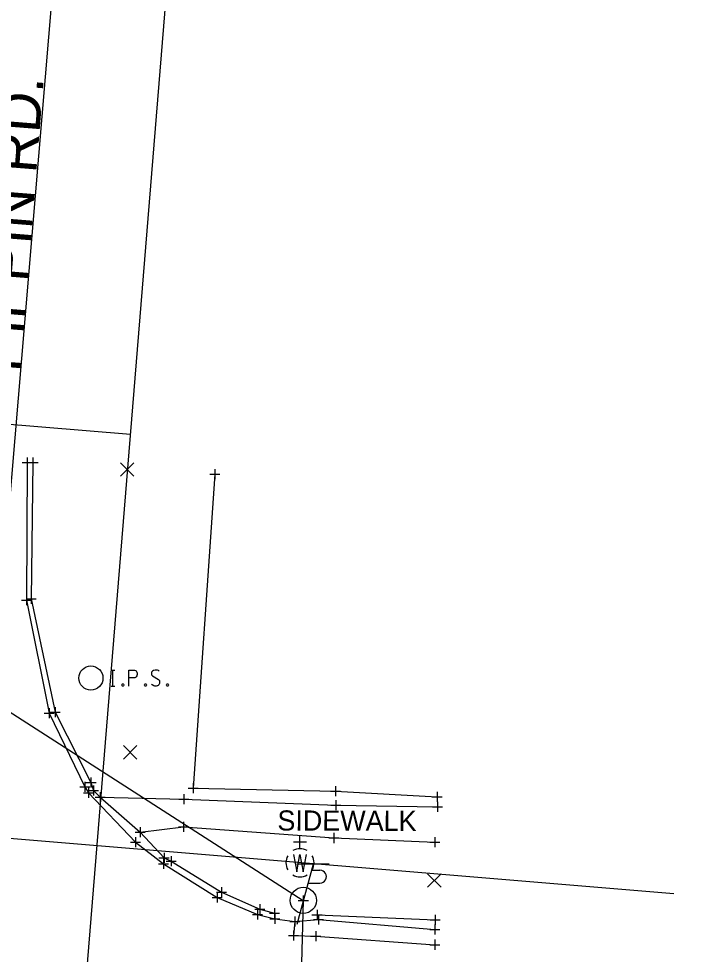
# Model space of a CAD drawing. Extents: x 1380440 to 1381945, y 468756 to 470369.
# Drawn here: x 1381547.1 to 1381614.9, y 469159.2 to 469252.2 of the extents above; entities that cross this region are included whole.
import ezdxf

# ---------------------------------------------------------------- set-up
doc = ezdxf.new("R2010")
doc.units = 0
for name, color, linetype in [('DR_P_Headwall', 7, 'Continuous'), ('DR_X_Cells', 7, 'Continuous'), ('GE_P_Driveway_CL', 7, 'Continuous'), ('GK_Drainage_Nodes', 7, 'Continuous'), ('PV_P_Walk', 7, 'Continuous'), ('PV_X_COP', 7, 'Continuous'), ('RW_P_Const_Limits', 7, 'Continuous'), ('RW_P_Esmt_TMP', 7, 'Continuous'), ('SH_Named_Boundary', 7, 'Continuous'), ('UT_X_Overhead_Combined', 7, 'Continuous'), ('UT_X_Overhead_Telecom', 7, 'Continuous'), ('UT_X_Sanitary_Line', 7, 'Continuous'), ('UT_X_Water', 7, 'Continuous'), ('X-SUBDIVISION', 7, 'Continuous')]:
    doc.layers.add(name, color=color, linetype=linetype)

msp = doc.modelspace()

# ---------------------------------------------------------------- linework, layer by layer
at = {"layer": 'DR_P_Headwall'}
for points in [[(1381555.163, 469174.772), (1381563.486, 469174.57), (1381578.581, 469173.981), (1381588.68, 469173.803)], [(1381559.145, 469171.286), (1381563.442, 469171.834), (1381578.369, 469170.714), (1381588.407, 469170.306)]]:
    msp.add_lwpolyline(points, dxfattribs=at)
at = {"layer": 'DR_X_Cells'}
for points in [[(1381548.49, 469208.03), (1381548.306, 469194.482), (1381550.699, 469183.223), (1381554.254, 469176.228), (1381554.509, 469175.447), (1381555.163, 469174.772), (1381559.145, 469171.286), (1381561.509, 469168.737), (1381562.206, 469168.402), (1381567.213, 469165.329), (1381571.015, 469163.646), (1381572.481, 469163.233)], [(1381576.709, 469163.068), (1381588.441, 469162.58)], [(1381574.504, 469162.404), (1381576.844, 469162.602), (1381588.409, 469161.614)]]:
    msp.add_lwpolyline(points, dxfattribs=at)
at = {"layer": 'GE_P_Driveway_CL'}
for p, q in [((1381557.169, 469206.688), (1381558.503, 469208.023)), ((1381557.169, 469208.023), (1381558.503, 469206.688)), ((1381557.47, 469178.556), (1381558.804, 469179.891)), ((1381557.47, 469179.891), (1381558.804, 469178.556)), ((1381587.693, 469165.821), (1381589.027, 469167.156)), ((1381587.693, 469167.156), (1381589.027, 469165.821))]:
    msp.add_line(p, q, dxfattribs=at)
at = {"layer": 'GK_Drainage_Nodes'}
msp.add_lwpolyline([(1381566.566, 469206.867), (1381564.411, 469175.674), (1381578.548, 469175.359), (1381588.639, 469174.792)], dxfattribs=at)
at = {"layer": 'PV_P_Walk'}
for points in [[(1381556.263, 469187.412), (1381556.616, 469187.412)], [(1381556.439, 469185.812), (1381556.439, 469187.412)], [(1381558.005, 469185.812), (1381558.005, 469187.412), (1381558.534, 469187.412), (1381558.589, 469187.4), (1381558.666, 469187.374), (1381558.699, 469187.349), (1381558.732, 469187.324), (1381558.776, 469187.261), (1381558.809, 469187.198), (1381558.831, 469187.097), (1381558.831, 469186.946), (1381558.82, 469186.896), (1381558.798, 469186.82), (1381558.754, 469186.732), (1381558.71, 469186.694), (1381558.677, 469186.669), (1381558.622, 469186.644), (1381558.534, 469186.631), (1381558.005, 469186.631)], [(1381561.014, 469187.299), (1381560.992, 469187.324), (1381560.959, 469187.349), (1381560.86, 469187.387), (1381560.738, 469187.412), (1381560.65, 469187.412), (1381560.617, 469187.412), (1381560.474, 469187.374), (1381560.353, 469187.299), (1381560.275, 469187.198), (1381560.253, 469187.097), (1381560.253, 469187.022), (1381560.275, 469186.921), (1381560.364, 469186.833), (1381560.97, 469186.455), (1381561.025, 469186.405), (1381561.047, 469186.354), (1381561.069, 469186.279), (1381561.069, 469186.203), (1381561.058, 469186.127), (1381561.047, 469186.077), (1381561.025, 469186.014), (1381561.003, 469185.964), (1381560.981, 469185.926), (1381560.948, 469185.888), (1381560.915, 469185.863), (1381560.871, 469185.838), (1381560.838, 469185.825), (1381560.738, 469185.812), (1381560.584, 469185.812), (1381560.485, 469185.838), (1381560.341, 469185.926), (1381560.253, 469186.001)], [(1381557.398, 469186.027), (1381557.453, 469186.027), (1381557.487, 469186.001), (1381557.52, 469185.951), (1381557.52, 469185.888), (1381557.487, 469185.838), (1381557.453, 469185.812), (1381557.398, 469185.812), (1381557.365, 469185.838), (1381557.332, 469185.888), (1381557.332, 469185.951), (1381557.365, 469186.001), (1381557.398, 469186.027)], [(1381559.647, 469186.027), (1381559.702, 469186.027), (1381559.735, 469186.001), (1381559.768, 469185.951), (1381559.768, 469185.888), (1381559.735, 469185.838), (1381559.702, 469185.812), (1381559.647, 469185.812), (1381559.614, 469185.838), (1381559.581, 469185.888), (1381559.581, 469185.951), (1381559.614, 469186.001), (1381559.647, 469186.027)], [(1381561.83, 469186.027), (1381561.885, 469186.027), (1381561.918, 469186.001), (1381561.951, 469185.951), (1381561.951, 469185.888), (1381561.918, 469185.838), (1381561.885, 469185.812), (1381561.83, 469185.812), (1381561.796, 469185.838), (1381561.764, 469185.888), (1381561.764, 469185.951), (1381561.796, 469186.001), (1381561.83, 469186.027)], [(1381556.263, 469185.812), (1381556.616, 469185.812)]]:
    msp.add_lwpolyline(points, dxfattribs=at)
msp.add_circle((1381554.244, 469186.611), 1.2, dxfattribs=at)
at = {"layer": 'PV_X_COP'}
for p, q in [((1381576.312, 469168.111), (1381574.706, 469162.111)), ((1381577.912, 469168.111), (1381574.712, 469168.111)), ((1381576.152, 469167.511), (1381577.002, 469167.511)), ((1381575.811, 469166.236), (1381577.002, 469166.236))]:
    msp.add_line(p, q, dxfattribs=at)
msp.add_circle((1381575.349, 469164.511), 1.3, dxfattribs=at)
msp.add_arc((1381577.015, 469166.874), 0.638, 268.8767, 91.1233, dxfattribs=at)
at = {"layer": 'RW_P_Const_Limits'}
for p, q in [((1381575.652, 469170.283), (1381574.38, 469170.283)), ((1381575.017, 469169.646), (1381575.017, 469170.918)), ((1381575.017, 469168.246), (1381575.017, 469168.246))]:
    msp.add_line(p, q, dxfattribs=at)
msp.add_lwpolyline([(1381574.38, 469169.066), (1381574.699, 469167.343), (1381575.017, 469169.066), (1381575.337, 469167.343), (1381575.654, 469169.066)], dxfattribs=at)
for start, end in [(60.01836, 120.01574), (150.01836, 209.98164), (330.01836, 29.98164), (239.98426, 299.98164)]:
    msp.add_arc((1381575.017, 469168.248), 1.4, start, end, dxfattribs=at)
at = {"layer": 'RW_P_Esmt_TMP'}
msp.add_lwpolyline([(1381547.909, 469208.051), (1381547.84, 469194.367), (1381550.09, 469183.128), (1381553.65, 469175.8), (1381554.007, 469175.192), (1381558.668, 469170.29), (1381561.464, 469168.133), (1381566.798, 469164.8), (1381570.8, 469163.096), (1381572.509, 469162.677), (1381574.504, 469162.404), (1381574.384, 469161.02), (1381576.576, 469160.953), (1381588.411, 469160.105)], dxfattribs=at)
at = {"layer": 'SH_Named_Boundary'}
for p, q in [((1381547.909, 469208.551), (1381547.909, 469207.551)), ((1381548.49, 469208.53), (1381548.49, 469207.53)), ((1381547.409, 469208.051), (1381548.409, 469208.051)), ((1381547.909, 469208.051), (1381547.909, 469208.051)), ((1381547.99, 469208.03), (1381548.99, 469208.03)), ((1381548.49, 469208.03), (1381548.49, 469208.03)), ((1381566.566, 469207.367), (1381566.566, 469206.367)), ((1381566.066, 469206.867), (1381567.066, 469206.867)), ((1381566.566, 469206.867), (1381566.566, 469206.867)), ((1381547.34, 469194.367), (1381548.34, 469194.367)), ((1381547.34, 469194.367), (1381548.34, 469194.367)), ((1381547.806, 469194.482), (1381548.806, 469194.482)), ((1381547.806, 469194.482), (1381548.806, 469194.482)), ((1381547.84, 469194.867), (1381547.84, 469193.867)), ((1381547.84, 469194.867), (1381547.84, 469193.867)), ((1381547.84, 469194.367), (1381547.84, 469194.367)), ((1381547.84, 469194.367), (1381547.84, 469194.367)), ((1381548.306, 469194.982), (1381548.306, 469193.982)), ((1381548.306, 469194.982), (1381548.306, 469193.982)), ((1381548.306, 469194.482), (1381548.306, 469194.482)), ((1381548.306, 469194.482), (1381548.306, 469194.482)), ((1381550.09, 469183.628), (1381550.09, 469182.628)), ((1381550.199, 469183.223), (1381551.199, 469183.223)), ((1381550.699, 469183.723), (1381550.699, 469182.723)), ((1381550.699, 469183.223), (1381550.699, 469183.223)), ((1381549.59, 469183.128), (1381550.59, 469183.128)), ((1381550.09, 469183.128), (1381550.09, 469183.128)), ((1381554.254, 469176.728), (1381554.254, 469175.728)), ((1381554.254, 469176.728), (1381554.254, 469175.728)), ((1381553.15, 469175.8), (1381554.15, 469175.8)), ((1381553.15, 469175.8), (1381554.15, 469175.8)), ((1381553.65, 469176.3), (1381553.65, 469175.3)), ((1381553.65, 469176.3), (1381553.65, 469175.3)), ((1381553.65, 469175.8), (1381553.65, 469175.8)), ((1381553.65, 469175.8), (1381553.65, 469175.8)), ((1381553.754, 469176.228), (1381554.754, 469176.228)), ((1381553.754, 469176.228), (1381554.754, 469176.228)), ((1381554.007, 469175.692), (1381554.007, 469174.692)), ((1381554.254, 469176.228), (1381554.254, 469176.228)), ((1381554.254, 469176.228), (1381554.254, 469176.228)), ((1381554.509, 469175.947), (1381554.509, 469174.947)), ((1381564.411, 469176.174), (1381564.411, 469175.174)), ((1381578.548, 469175.859), (1381578.548, 469174.859)), ((1381553.507, 469175.192), (1381554.507, 469175.192)), ((1381554.007, 469175.192), (1381554.007, 469175.192)), ((1381554.009, 469175.447), (1381555.009, 469175.447)), ((1381554.509, 469175.447), (1381554.509, 469175.447)), ((1381554.663, 469174.772), (1381555.663, 469174.772)), ((1381554.663, 469174.772), (1381555.663, 469174.772)), ((1381555.163, 469175.272), (1381555.163, 469174.272)), ((1381555.163, 469175.272), (1381555.163, 469174.272)), ((1381555.163, 469174.772), (1381555.163, 469174.772)), ((1381555.163, 469174.772), (1381555.163, 469174.772)), ((1381563.486, 469175.07), (1381563.486, 469174.07)), ((1381563.911, 469175.674), (1381564.911, 469175.674)), ((1381564.411, 469175.674), (1381564.411, 469175.674)), ((1381578.048, 469175.359), (1381579.048, 469175.359)), ((1381578.548, 469175.359), (1381578.548, 469175.359)), ((1381588.139, 469174.792), (1381589.139, 469174.792)), ((1381588.639, 469175.292), (1381588.639, 469174.292)), ((1381588.639, 469174.792), (1381588.639, 469174.792)), ((1381562.986, 469174.57), (1381563.986, 469174.57)), ((1381563.486, 469174.57), (1381563.486, 469174.57)), ((1381578.081, 469173.981), (1381579.081, 469173.981)), ((1381578.581, 469174.481), (1381578.581, 469173.481)), ((1381578.581, 469173.981), (1381578.581, 469173.981)), ((1381588.68, 469174.303), (1381588.68, 469173.303)), ((1381588.18, 469173.803), (1381589.18, 469173.803)), ((1381588.68, 469173.803), (1381588.68, 469173.803)), ((1381563.442, 469172.334), (1381563.442, 469171.334)), ((1381558.645, 469171.286), (1381559.645, 469171.286)), ((1381558.645, 469171.286), (1381559.645, 469171.286)), ((1381559.145, 469171.786), (1381559.145, 469170.786)), ((1381559.145, 469171.786), (1381559.145, 469170.786)), ((1381559.145, 469171.286), (1381559.145, 469171.286)), ((1381559.145, 469171.286), (1381559.145, 469171.286)), ((1381562.942, 469171.834), (1381563.942, 469171.834)), ((1381563.442, 469171.834), (1381563.442, 469171.834)), ((1381578.369, 469171.214), (1381578.369, 469170.214)), ((1381558.168, 469170.29), (1381559.168, 469170.29)), ((1381558.668, 469170.79), (1381558.668, 469169.79)), ((1381558.668, 469170.29), (1381558.668, 469170.29)), ((1381577.869, 469170.714), (1381578.869, 469170.714)), ((1381578.369, 469170.714), (1381578.369, 469170.714)), ((1381587.907, 469170.306), (1381588.907, 469170.306)), ((1381588.407, 469170.806), (1381588.407, 469169.806)), ((1381588.407, 469170.306), (1381588.407, 469170.306)), ((1381561.509, 469169.237), (1381561.509, 469168.237)), ((1381561.009, 469168.737), (1381562.009, 469168.737)), ((1381561.464, 469168.633), (1381561.464, 469167.633)), ((1381561.509, 469168.737), (1381561.509, 469168.737)), ((1381561.706, 469168.402), (1381562.706, 469168.402)), ((1381562.206, 469168.902), (1381562.206, 469167.902)), ((1381562.206, 469168.402), (1381562.206, 469168.402)), ((1381560.964, 469168.133), (1381561.964, 469168.133)), ((1381561.464, 469168.133), (1381561.464, 469168.133)), ((1381567.213, 469165.829), (1381567.213, 469164.829)), ((1381566.298, 469164.8), (1381567.298, 469164.8)), ((1381566.713, 469165.329), (1381567.713, 469165.329)), ((1381566.798, 469165.3), (1381566.798, 469164.3)), ((1381566.798, 469164.8), (1381566.798, 469164.8)), ((1381567.213, 469165.329), (1381567.213, 469165.329)), ((1381575.349, 469165.011), (1381575.349, 469164.011)), ((1381575.349, 469165.011), (1381575.349, 469164.011)), ((1381570.515, 469163.646), (1381571.515, 469163.646)), ((1381571.015, 469164.146), (1381571.015, 469163.146)), ((1381571.015, 469163.646), (1381571.015, 469163.646)), ((1381572.481, 469163.733), (1381572.481, 469162.733)), ((1381574.849, 469164.511), (1381575.849, 469164.511)), ((1381574.849, 469164.511), (1381575.849, 469164.511)), ((1381575.349, 469164.511), (1381575.349, 469164.511)), ((1381575.349, 469164.511), (1381575.349, 469164.511)), ((1381570.3, 469163.096), (1381571.3, 469163.096)), ((1381570.8, 469163.596), (1381570.8, 469162.596)), ((1381570.8, 469163.096), (1381570.8, 469163.096)), ((1381571.981, 469163.233), (1381572.981, 469163.233)), ((1381572.009, 469162.677), (1381573.009, 469162.677)), ((1381572.481, 469163.233), (1381572.481, 469163.233)), ((1381572.509, 469163.177), (1381572.509, 469162.177)), ((1381572.509, 469162.677), (1381572.509, 469162.677)), ((1381574.504, 469162.904), (1381574.504, 469161.904)), ((1381574.504, 469162.904), (1381574.504, 469161.904)), ((1381576.209, 469163.068), (1381577.209, 469163.068)), ((1381576.709, 469163.568), (1381576.709, 469162.568)), ((1381576.709, 469163.068), (1381576.709, 469163.068)), ((1381576.844, 469163.102), (1381576.844, 469162.102)), ((1381588.441, 469163.08), (1381588.441, 469162.08)), ((1381574.004, 469162.404), (1381575.004, 469162.404)), ((1381574.004, 469162.404), (1381575.004, 469162.404)), ((1381574.504, 469162.404), (1381574.504, 469162.404)), ((1381574.504, 469162.404), (1381574.504, 469162.404)), ((1381576.344, 469162.602), (1381577.344, 469162.602)), ((1381576.844, 469162.602), (1381576.844, 469162.602)), ((1381587.941, 469162.58), (1381588.941, 469162.58)), ((1381588.409, 469162.114), (1381588.409, 469161.114)), ((1381588.441, 469162.58), (1381588.441, 469162.58)), ((1381573.884, 469161.02), (1381574.884, 469161.02)), ((1381574.384, 469161.52), (1381574.384, 469160.52)), ((1381574.384, 469161.02), (1381574.384, 469161.02)), ((1381576.076, 469160.953), (1381577.076, 469160.953)), ((1381576.576, 469161.453), (1381576.576, 469160.453)), ((1381576.576, 469160.953), (1381576.576, 469160.953)), ((1381587.909, 469161.614), (1381588.909, 469161.614)), ((1381588.409, 469161.614), (1381588.409, 469161.614)), ((1381587.911, 469160.105), (1381588.911, 469160.105)), ((1381588.411, 469160.605), (1381588.411, 469159.605)), ((1381588.411, 469160.105), (1381588.411, 469160.105))]:
    msp.add_line(p, q, dxfattribs=at)
at = {"layer": 'UT_X_Overhead_Combined'}
msp.add_lwpolyline([(1381515.279, 469203.101), (1381575.349, 469164.511)], dxfattribs=at)
at = {"layer": 'UT_X_Overhead_Telecom'}
msp.add_line((1381575.349, 469164.511), (1381574.608, 469136.773), dxfattribs=at)
at = {"layer": 'UT_X_Sanitary_Line'}
for p, q in [((1381552.86, 469145.474), (1381576.006, 469430.094)), ((1381558.175, 469210.835), (1381509.187, 469214.819))]:
    msp.add_line(p, q, dxfattribs=at)
at = {"layer": 'UT_X_Water'}
for p, q in [((1381545.409, 469194.714), (1381630.263, 470209.692)), ((1381612.166, 469165.147), (1381543.419, 469170.882))]:
    msp.add_line(p, q, dxfattribs=at)

# ---------------------------------------------------------------- texts
at = {"layer": 'X-SUBDIVISION'}
for s, height, rotation, p in [('PIPPIN RD.', 4.1667, 85.44278, (1381547.236, 469216.961)), ('SIDEWALK', 2, 359.81862, (1381572.771, 469171.456))]:
    msp.add_text(s, height=height, rotation=rotation, dxfattribs=at).set_placement(p)

doc.saveas('drawing.dxf')
